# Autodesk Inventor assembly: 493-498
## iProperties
Author: Administrator
Created: 2002-03
Part Number: 493-498
Document SubType Name: Assembly
Designer: Administrator
Control State: 0
Master: False
Checked Out: False
PropertySet Name: Design Tracking Control
Shininess: 64.0
Angle Display Precision: 2
Document Length Units: 11272
Document Angle Units: 11286
Document Time Units: 11279
Document Mass Units: 11290
Document Length Units Precision: 3
Document Angle Units Precision: 2
Compacted: True
PropertySet Name: _Private Model Information
Density: 0.0
Volumn: 0.0
Area: 0.0
PropertySet Name: Model Information
